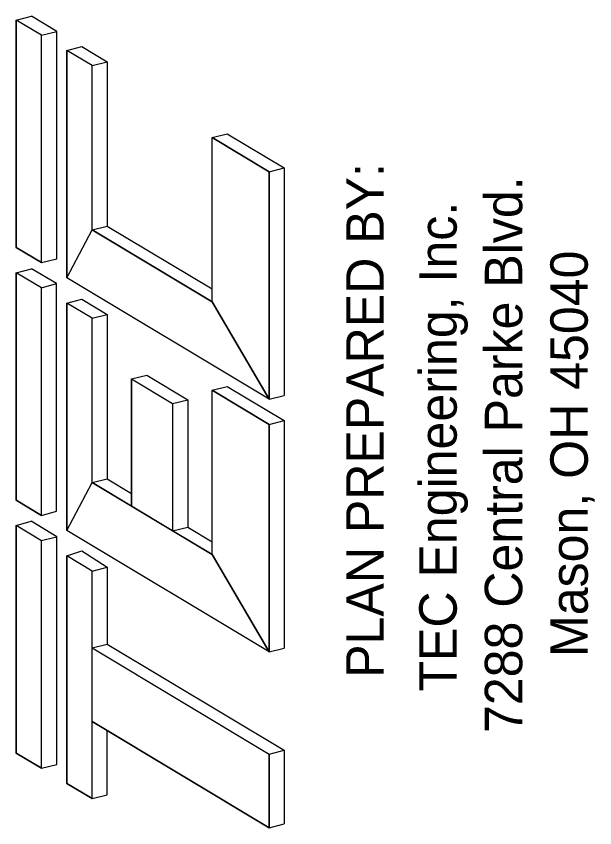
# Model space of a CAD drawing. Extents: x -30.3 to 21.6, y 6.6 to 27.2.
# Drawn here: x 10.656 to 11.892, y 8.733 to 10.467 of the extents above; entities that cross this region are included whole.
import ezdxf

# ---------------------------------------------------------------- set-up
doc = ezdxf.new("R2010")
doc.units = 0
doc.layers.add('Default', color=7, linetype='Continuous')
doc.layers.add('DR_X_Cells', color=7, linetype='Continuous')

msp = doc.modelspace()

# ---------------------------------------------------------------- linework, layer by layer
at = {"layer": 'DR_X_Cells'}
for p, q in [((10.6559, 10.4591), (10.6883, 10.4672)), ((10.6559, 9.9731), (10.6559, 10.4591)), ((10.7099, 10.4267), (10.6559, 10.4591)), ((10.7423, 10.4348), (10.6883, 10.4672)), ((10.7099, 10.4267), (10.7423, 10.4348)), ((10.7099, 9.9407), (10.7099, 10.4267)), ((10.7423, 9.9488), (10.7423, 10.4348)), ((10.7639, 10.3943), (10.7963, 10.4024)), ((10.8179, 10.3619), (10.7639, 10.3943)), ((10.7639, 9.9083), (10.7639, 10.3943)), ((10.7963, 10.4024), (10.8503, 10.37)), ((10.8179, 10.3619), (10.8503, 10.37)), ((10.8503, 10.37), (10.8503, 10.019)), ((10.8179, 10.0109), (10.8179, 10.3619)), ((11.0744, 10.208), (11.1068, 10.2161)), ((11.1068, 10.2161), (11.2283, 10.1432)), ((11.0744, 9.857), (11.0744, 10.208)), ((11.1959, 10.1351), (11.0744, 10.208)), ((11.1959, 10.1351), (11.2283, 10.1432)), ((11.2283, 10.1432), (11.2283, 9.6572)), ((11.1959, 9.6491), (11.1959, 10.1351)), ((10.8179, 10.0109), (10.8503, 10.019)), ((11.0744, 9.857), (10.8179, 10.0109)), ((10.8503, 10.019), (11.0744, 9.8845)), ((10.7099, 9.9407), (10.6559, 9.9731)), ((10.7099, 9.9407), (10.7423, 9.9488)), ((10.6559, 9.9191), (10.6883, 9.9272)), ((10.6559, 9.4331), (10.6559, 9.9191)), ((10.7099, 9.8867), (10.6559, 9.9191)), ((10.7418, 9.8961), (10.6883, 9.9272)), ((11.1959, 9.6491), (10.7639, 9.9083)), ((10.7099, 9.8867), (10.7418, 9.8961)), ((10.7099, 9.4007), (10.7099, 9.8867)), ((10.7418, 9.4101), (10.7418, 9.8961)), ((10.7639, 9.8543), (10.7963, 9.8624)), ((10.7639, 9.3683), (10.7639, 9.8543)), ((10.8179, 9.8219), (10.7639, 9.8543)), ((10.7963, 9.8624), (10.8503, 9.83)), ((10.8179, 9.8219), (10.8503, 9.83)), ((10.8179, 9.4709), (10.8179, 9.8219)), ((10.8503, 9.83), (10.8503, 9.479)), ((10.9023, 9.6926), (10.9347, 9.7007)), ((10.9023, 9.6926), (10.9023, 9.4203)), ((10.9023, 9.6926), (10.99, 9.6399)), ((10.9347, 9.7007), (11.0224, 9.648)), ((11.0744, 9.668), (11.1068, 9.6761)), ((11.1068, 9.6761), (11.2283, 9.6032)), ((11.0744, 9.317), (11.0744, 9.668)), ((11.1959, 9.5951), (11.0744, 9.668)), ((10.99, 9.6399), (11.0224, 9.648)), ((11.0224, 9.648), (11.0224, 9.3757)), ((11.1959, 9.6491), (11.2283, 9.6572)), ((10.99, 9.6399), (10.99, 9.3676)), ((11.1959, 9.5951), (11.2283, 9.6032)), ((11.1959, 9.1091), (11.1959, 9.5951)), ((11.2283, 9.6032), (11.2283, 9.1172)), ((10.8179, 9.4709), (10.8503, 9.479)), ((10.9023, 9.4203), (10.8179, 9.4709)), ((10.8503, 9.479), (10.9023, 9.4478)), ((10.7099, 9.4007), (10.6559, 9.4331)), ((10.7099, 9.4007), (10.7418, 9.4101)), ((10.6559, 9.3791), (10.6878, 9.3885)), ((10.7423, 9.3548), (10.6878, 9.3885)), ((10.6559, 8.8931), (10.6559, 9.3791)), ((10.7099, 9.3467), (10.6559, 9.3791)), ((11.1959, 9.1091), (10.7639, 9.3683)), ((10.99, 9.3676), (11.0224, 9.3757)), ((11.0744, 9.317), (10.99, 9.3676)), ((11.0224, 9.3757), (11.0744, 9.3445)), ((10.7094, 9.347), (10.7423, 9.3548)), ((10.7099, 8.8607), (10.7099, 9.3467)), ((10.7423, 8.8688), (10.7423, 9.3548)), ((10.7639, 9.3143), (10.7958, 9.3251)), ((10.8179, 9.2819), (10.7639, 9.3143)), ((10.7639, 8.8283), (10.7639, 9.3143)), ((10.7958, 9.3251), (10.8503, 9.29)), ((10.8179, 9.2819), (10.8503, 9.29)), ((10.8179, 9.1176), (10.8179, 9.2819)), ((10.8503, 9.29), (10.8503, 9.1257)), ((10.8179, 9.1176), (10.8503, 9.1257)), ((10.8503, 9.1257), (11.2283, 8.8989)), ((10.8179, 9.1176), (11.1959, 8.8908)), ((11.1959, 9.1091), (11.2283, 9.1172)), ((10.8179, 8.9602), (11.1959, 8.7334)), ((10.8179, 8.7959), (10.8179, 8.9602)), ((10.8503, 8.804), (10.8503, 8.9407)), ((11.1959, 8.8908), (11.2283, 8.8989)), ((11.2283, 8.8989), (11.2283, 8.7415)), ((10.7099, 8.8607), (10.6559, 8.8931)), ((11.1959, 8.7334), (11.1959, 8.8908)), ((10.7099, 8.8607), (10.7423, 8.8688)), ((10.8179, 8.7959), (10.7639, 8.8283)), ((10.8179, 8.7959), (10.8503, 8.804)), ((11.1959, 8.7334), (11.2283, 8.7415))]:
    msp.add_line(p, q, dxfattribs=at)
for points in [[(10.6559, 9.9731), (10.7099, 9.9407), (10.7099, 10.4267), (10.6559, 10.4591)], [(10.7639, 9.9083), (10.8179, 10.0109), (10.8179, 10.3619), (10.7639, 10.3943)], [(11.1959, 9.6491), (11.0744, 9.857), (11.0744, 10.208), (11.1959, 10.1351)], [(10.7639, 9.9083), (10.8179, 10.0109), (11.0744, 9.857), (11.1959, 9.6491)], [(10.6559, 9.4331), (10.7099, 9.4007), (10.7099, 9.8867), (10.6559, 9.9191)], [(10.7639, 9.3683), (10.8179, 9.4709), (10.8179, 9.8219), (10.7639, 9.8543)], [(10.9023, 9.4203), (10.9023, 9.6926), (10.99, 9.6399), (10.99, 9.3676)], [(11.1959, 9.1091), (11.0744, 9.317), (11.0744, 9.668), (11.1959, 9.5951)], [(10.7639, 9.3683), (10.8179, 9.4709), (11.0744, 9.317), (11.1959, 9.1091)], [(10.6559, 8.8931), (10.7099, 8.8607), (10.7099, 9.3467), (10.6559, 9.3791)], [(10.7639, 8.8283), (10.8179, 8.7959), (10.8179, 9.2819), (10.7639, 9.3143)], [(10.8179, 8.9602), (10.8179, 9.1176), (11.1959, 8.8908), (11.1959, 8.7334)]]:
    msp.add_lwpolyline(points, close=True, dxfattribs=at)

# ---------------------------------------------------------------- texts
at = {"layer": 'Default'}
for s, p in [('PLAN PREPARED BY:', (11.4408, 9.0537)), ('7288 Central Parke Blvd.', (11.7368, 8.9358)), ('TEC Engineering, Inc.', (11.5968, 9.0243)), ('Mason, OH 45040', (11.8768, 9.0983))]:
    msp.add_text(s, height=0.08, rotation=90, dxfattribs=at).set_placement(p)

doc.saveas('drawing.dxf')
